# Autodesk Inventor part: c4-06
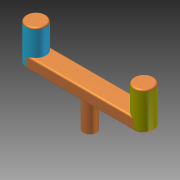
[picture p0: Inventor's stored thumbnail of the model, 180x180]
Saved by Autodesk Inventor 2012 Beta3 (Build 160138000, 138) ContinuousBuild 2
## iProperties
Created: 2010-11
Part Number: c4-06
Material: Default
Document SubType Name: Modeling
Designer: Beta-8540w
Density: 1 g/cm^3
Author: Beta-8540w
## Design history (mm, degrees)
sketch "Sketch1" dims "d4" = 27, "d5" = 6
  geometry: L1 (-16.5, -3)-(16.5, -3); L2 (16.5, -3)-(16.5, 3); L3 (16.5, 3)-(-16.5, 3); L4 (-16.5, 3)-(-16.5, -3); C1 r 1.986 at (0, 0); 4 further points
  constraints: 8 end point, 3 midpoint, 3 vertical alignment, 2 parallel, 1 centre point, 1 coincident, 1 horizontal, 1 horizontal alignment, 1 perpendicular, 4 other
extrude "Extrusion1" new body sketch "Sketch1" distance "d0" = 8; taper "d1" = 0 deg
extrude "Extrusion2" join sketch "Sketch1" distance "d2" = 3.5; taper "d3" = 0 deg
extrude "Extrusion3" join sketch "Sketch1" distance "d6" = 12.75; taper "d7" = 0 deg
fillet "Fillet1" dims "d8" = 0.5
fillet "Fillet2" dims "d9" = 0.5
body "Solid1"
